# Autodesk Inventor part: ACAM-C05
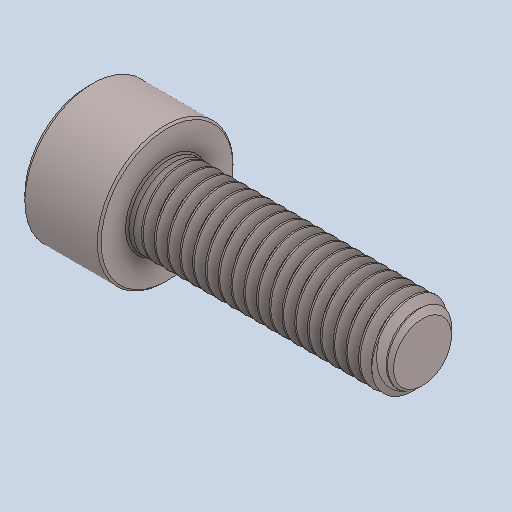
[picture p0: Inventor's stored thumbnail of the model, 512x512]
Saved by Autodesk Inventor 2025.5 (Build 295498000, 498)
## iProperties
Created: 2025-07
Part Number: ACAM-C05
Material: Genérico
Description: Tornillo Allen M5×16
Document SubType Name: Modeling
Designer: Luis M
Density: 1 g/cm^3
Appearance: Valor por defecto
Sending System: SolidWorks 2022
Preprocessor: SwSTEP 2.0
Material_BOM: Por especificar
Proceso_BOM: Comercial
Title: TORNILLO ALLEN CABEZA HEXAGONAL M5-0.8-16.STEP
Revision Number: ANY
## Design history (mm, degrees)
feature "Revolución2"
node "Sólido1"
